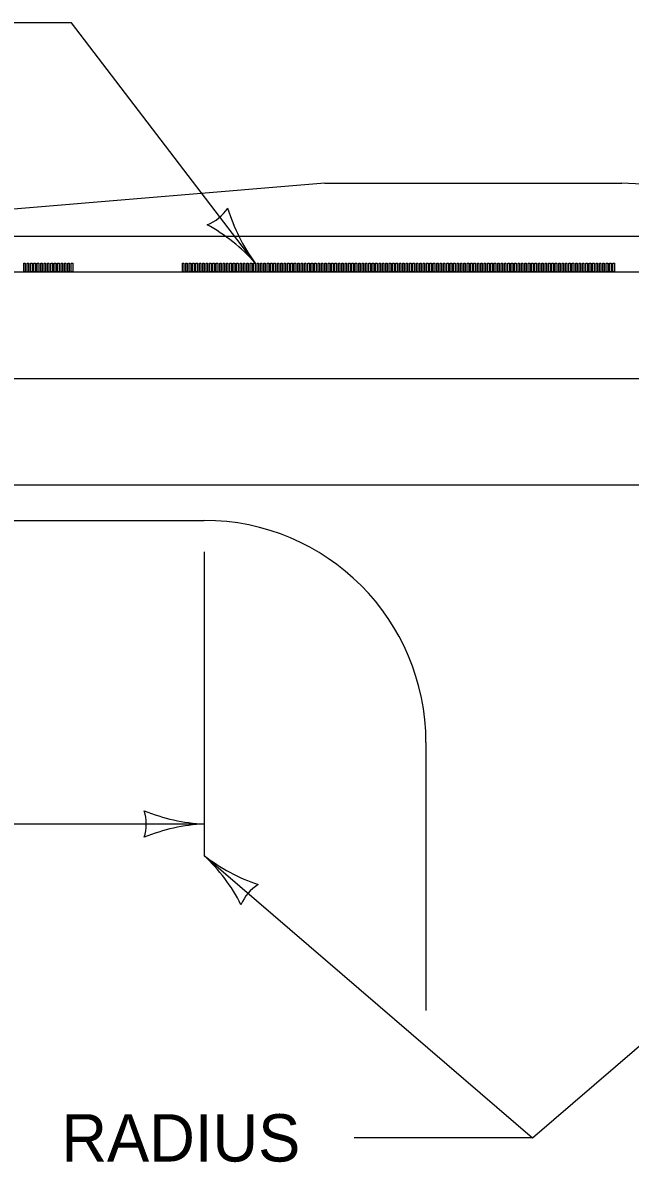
# Model space of a CAD drawing. Extents: x 49991.4 to 50021, y 49987.6 to 50011.4.
# Drawn here: x 50006.534 to 50007.305, y 49991.816 to 49993.26 of the extents above; entities that cross this region are included whole.
import ezdxf

# ---------------------------------------------------------------- set-up
doc = ezdxf.new("R2010")
doc.units = 0
for name, color, linetype in [('Level 1', 7, 'Continuous'), ('Level 2', 7, 'Continuous'), ('Level 3', 7, 'Continuous')]:
    doc.layers.add(name, color=color, linetype=linetype)

msp = doc.modelspace()

# ---------------------------------------------------------------- linework, layer by layer
at = {"layer": 'Level 1'}
for p, q in [((50006.9175, 49993.0571), (50005.5675, 49992.9446)), ((50006.9175, 49993.0571), (50007.294, 49993.0571)), ((50009.544, 49992.9446), (50007.294, 49993.0571)), ((50005.1251, 49992.9896), (50011.5103, 49992.9896)), ((50005.1251, 49992.9446), (50011.5103, 49992.9446)), ((50005.1251, 49992.8096), (50011.5103, 49992.8096)), ((50005.1253, 49992.6746), (50011.5103, 49992.6746)), ((50005.1253, 49992.6296), (50006.7645, 49992.6296)), ((50007.0457, 49992.3483), (50007.0457, 49992.0088))]:
    msp.add_line(p, q, dxfattribs=at)
for points in [[(50006.5374, 49992.9446), (50006.5355, 49992.9446), (50006.5355, 49992.9558), (50006.5374, 49992.9558)], [(50006.5417, 49992.9446), (50006.5398, 49992.9446), (50006.5398, 49992.9558), (50006.5417, 49992.9558)], [(50006.546, 49992.9446), (50006.5441, 49992.9446), (50006.5441, 49992.9558), (50006.546, 49992.9558)], [(50006.5503, 49992.9446), (50006.5484, 49992.9446), (50006.5484, 49992.9558), (50006.5503, 49992.9558)], [(50006.5546, 49992.9446), (50006.5527, 49992.9446), (50006.5527, 49992.9558), (50006.5546, 49992.9558)], [(50006.5589, 49992.9446), (50006.557, 49992.9446), (50006.557, 49992.9558), (50006.5589, 49992.9558)], [(50006.5632, 49992.9446), (50006.5613, 49992.9446), (50006.5613, 49992.9558), (50006.5632, 49992.9558)], [(50006.5675, 49992.9446), (50006.5656, 49992.9446), (50006.5656, 49992.9558), (50006.5675, 49992.9558)], [(50006.5718, 49992.9446), (50006.5699, 49992.9446), (50006.5699, 49992.9558), (50006.5718, 49992.9558)], [(50006.5761, 49992.9446), (50006.5742, 49992.9446), (50006.5742, 49992.9558), (50006.5761, 49992.9558)], [(50006.5804, 49992.9446), (50006.5785, 49992.9446), (50006.5785, 49992.9558), (50006.5804, 49992.9558)], [(50006.5847, 49992.9446), (50006.5828, 49992.9446), (50006.5828, 49992.9558), (50006.5847, 49992.9558)], [(50006.589, 49992.9446), (50006.5871, 49992.9446), (50006.5871, 49992.9558), (50006.589, 49992.9558)], [(50006.5933, 49992.9446), (50006.5914, 49992.9446), (50006.5914, 49992.9558), (50006.5933, 49992.9558)], [(50006.5976, 49992.9446), (50006.5957, 49992.9446), (50006.5957, 49992.9558), (50006.5976, 49992.9558)], [(50006.7387, 49992.9446), (50006.7368, 49992.9446), (50006.7368, 49992.9558), (50006.7387, 49992.9558)], [(50006.743, 49992.9446), (50006.7411, 49992.9446), (50006.7411, 49992.9558), (50006.743, 49992.9558)], [(50006.7473, 49992.9446), (50006.7454, 49992.9446), (50006.7454, 49992.9558), (50006.7473, 49992.9558)], [(50006.7516, 49992.9446), (50006.7497, 49992.9446), (50006.7497, 49992.9558), (50006.7516, 49992.9558)], [(50006.7559, 49992.9446), (50006.754, 49992.9446), (50006.754, 49992.9558), (50006.7559, 49992.9558)], [(50006.7602, 49992.9446), (50006.7583, 49992.9446), (50006.7583, 49992.9558), (50006.7602, 49992.9558)], [(50006.7645, 49992.9446), (50006.7626, 49992.9446), (50006.7626, 49992.9558), (50006.7645, 49992.9558)], [(50006.7688, 49992.9446), (50006.7669, 49992.9446), (50006.7669, 49992.9558), (50006.7688, 49992.9558)], [(50006.7731, 49992.9446), (50006.7712, 49992.9446), (50006.7712, 49992.9558), (50006.7731, 49992.9558)], [(50006.7774, 49992.9446), (50006.7755, 49992.9446), (50006.7755, 49992.9558), (50006.7774, 49992.9558)], [(50006.7817, 49992.9446), (50006.7798, 49992.9446), (50006.7798, 49992.9558), (50006.7817, 49992.9558)], [(50006.786, 49992.9446), (50006.7841, 49992.9446), (50006.7841, 49992.9558), (50006.786, 49992.9558)], [(50006.7903, 49992.9446), (50006.7884, 49992.9446), (50006.7884, 49992.9558), (50006.7903, 49992.9558)], [(50006.7946, 49992.9446), (50006.7927, 49992.9446), (50006.7927, 49992.9558), (50006.7946, 49992.9558)], [(50006.7989, 49992.9446), (50006.797, 49992.9446), (50006.797, 49992.9558), (50006.7989, 49992.9558)], [(50006.8032, 49992.9446), (50006.8013, 49992.9446), (50006.8013, 49992.9558), (50006.8032, 49992.9558)], [(50006.8075, 49992.9446), (50006.8056, 49992.9446), (50006.8056, 49992.9558), (50006.8075, 49992.9558)], [(50006.8118, 49992.9446), (50006.8099, 49992.9446), (50006.8099, 49992.9558), (50006.8118, 49992.9558)], [(50006.8161, 49992.9446), (50006.8142, 49992.9446), (50006.8142, 49992.9558), (50006.8161, 49992.9558)], [(50006.8204, 49992.9446), (50006.8185, 49992.9446), (50006.8185, 49992.9558), (50006.8204, 49992.9558)], [(50006.8247, 49992.9446), (50006.8228, 49992.9446), (50006.8228, 49992.9558), (50006.8247, 49992.9558)], [(50006.829, 49992.9446), (50006.8271, 49992.9446), (50006.8271, 49992.9558), (50006.829, 49992.9558)], [(50006.8333, 49992.9446), (50006.8314, 49992.9446), (50006.8314, 49992.9558), (50006.8333, 49992.9558)], [(50006.8376, 49992.9446), (50006.8357, 49992.9446), (50006.8357, 49992.9558), (50006.8376, 49992.9558)], [(50006.8419, 49992.9446), (50006.84, 49992.9446), (50006.84, 49992.9558), (50006.8419, 49992.9558)], [(50006.8462, 49992.9446), (50006.8443, 49992.9446), (50006.8443, 49992.9558), (50006.8462, 49992.9558)], [(50006.8505, 49992.9446), (50006.8486, 49992.9446), (50006.8486, 49992.9558), (50006.8505, 49992.9558)], [(50006.8548, 49992.9446), (50006.8529, 49992.9446), (50006.8529, 49992.9558), (50006.8548, 49992.9558)], [(50006.8591, 49992.9446), (50006.8572, 49992.9446), (50006.8572, 49992.9558), (50006.8591, 49992.9558)], [(50006.8634, 49992.9446), (50006.8615, 49992.9446), (50006.8615, 49992.9558), (50006.8634, 49992.9558)], [(50006.8677, 49992.9446), (50006.8658, 49992.9446), (50006.8658, 49992.9558), (50006.8677, 49992.9558)], [(50006.872, 49992.9446), (50006.8701, 49992.9446), (50006.8701, 49992.9558), (50006.872, 49992.9558)], [(50006.8763, 49992.9446), (50006.8744, 49992.9446), (50006.8744, 49992.9558), (50006.8763, 49992.9558)], [(50006.8806, 49992.9446), (50006.8787, 49992.9446), (50006.8787, 49992.9558), (50006.8806, 49992.9558)], [(50006.8849, 49992.9446), (50006.883, 49992.9446), (50006.883, 49992.9558), (50006.8849, 49992.9558)], [(50006.8892, 49992.9446), (50006.8873, 49992.9446), (50006.8873, 49992.9558), (50006.8892, 49992.9558)], [(50006.8935, 49992.9446), (50006.8916, 49992.9446), (50006.8916, 49992.9558), (50006.8935, 49992.9558)], [(50006.8978, 49992.9446), (50006.8959, 49992.9446), (50006.8959, 49992.9558), (50006.8978, 49992.9558)], [(50006.9021, 49992.9446), (50006.9002, 49992.9446), (50006.9002, 49992.9558), (50006.9021, 49992.9558)], [(50006.9064, 49992.9446), (50006.9045, 49992.9446), (50006.9045, 49992.9558), (50006.9064, 49992.9558)], [(50006.9107, 49992.9446), (50006.9088, 49992.9446), (50006.9088, 49992.9558), (50006.9107, 49992.9558)], [(50006.915, 49992.9446), (50006.9131, 49992.9446), (50006.9131, 49992.9558), (50006.915, 49992.9558)], [(50006.9193, 49992.9446), (50006.9174, 49992.9446), (50006.9174, 49992.9558), (50006.9193, 49992.9558)], [(50006.9236, 49992.9446), (50006.9217, 49992.9446), (50006.9217, 49992.9558), (50006.9236, 49992.9558)], [(50006.9279, 49992.9446), (50006.926, 49992.9446), (50006.926, 49992.9558), (50006.9279, 49992.9558)], [(50006.9322, 49992.9446), (50006.9303, 49992.9446), (50006.9303, 49992.9558), (50006.9322, 49992.9558)], [(50006.9365, 49992.9446), (50006.9346, 49992.9446), (50006.9346, 49992.9558), (50006.9365, 49992.9558)], [(50006.9408, 49992.9446), (50006.9389, 49992.9446), (50006.9389, 49992.9558), (50006.9408, 49992.9558)], [(50006.9451, 49992.9446), (50006.9432, 49992.9446), (50006.9432, 49992.9558), (50006.9451, 49992.9558)], [(50006.9494, 49992.9446), (50006.9475, 49992.9446), (50006.9475, 49992.9558), (50006.9494, 49992.9558)], [(50006.9537, 49992.9446), (50006.9518, 49992.9446), (50006.9518, 49992.9558), (50006.9537, 49992.9558)], [(50006.958, 49992.9446), (50006.9561, 49992.9446), (50006.9561, 49992.9558), (50006.958, 49992.9558)], [(50006.9623, 49992.9446), (50006.9604, 49992.9446), (50006.9604, 49992.9558), (50006.9623, 49992.9558)], [(50006.9666, 49992.9446), (50006.9647, 49992.9446), (50006.9647, 49992.9558), (50006.9666, 49992.9558)], [(50006.9709, 49992.9446), (50006.969, 49992.9446), (50006.969, 49992.9558), (50006.9709, 49992.9558)], [(50006.9752, 49992.9446), (50006.9733, 49992.9446), (50006.9733, 49992.9558), (50006.9752, 49992.9558)], [(50006.9795, 49992.9446), (50006.9776, 49992.9446), (50006.9776, 49992.9558), (50006.9795, 49992.9558)], [(50006.9838, 49992.9446), (50006.9819, 49992.9446), (50006.9819, 49992.9558), (50006.9838, 49992.9558)], [(50006.9881, 49992.9446), (50006.9862, 49992.9446), (50006.9862, 49992.9558), (50006.9881, 49992.9558)], [(50006.9924, 49992.9446), (50006.9905, 49992.9446), (50006.9905, 49992.9558), (50006.9924, 49992.9558)], [(50006.9967, 49992.9446), (50006.9948, 49992.9446), (50006.9948, 49992.9558), (50006.9967, 49992.9558)], [(50007.001, 49992.9446), (50006.9991, 49992.9446), (50006.9991, 49992.9558), (50007.001, 49992.9558)], [(50007.0053, 49992.9446), (50007.0034, 49992.9446), (50007.0034, 49992.9558), (50007.0053, 49992.9558)], [(50007.0096, 49992.9446), (50007.0077, 49992.9446), (50007.0077, 49992.9558), (50007.0096, 49992.9558)], [(50007.0139, 49992.9446), (50007.012, 49992.9446), (50007.012, 49992.9558), (50007.0139, 49992.9558)], [(50007.0182, 49992.9446), (50007.0163, 49992.9446), (50007.0163, 49992.9558), (50007.0182, 49992.9558)], [(50007.0225, 49992.9446), (50007.0206, 49992.9446), (50007.0206, 49992.9558), (50007.0225, 49992.9558)], [(50007.0268, 49992.9446), (50007.0249, 49992.9446), (50007.0249, 49992.9558), (50007.0268, 49992.9558)], [(50007.0311, 49992.9446), (50007.0292, 49992.9446), (50007.0292, 49992.9558), (50007.0311, 49992.9558)], [(50007.0354, 49992.9446), (50007.0335, 49992.9446), (50007.0335, 49992.9558), (50007.0354, 49992.9558)], [(50007.0397, 49992.9446), (50007.0378, 49992.9446), (50007.0378, 49992.9558), (50007.0397, 49992.9558)], [(50007.044, 49992.9446), (50007.0421, 49992.9446), (50007.0421, 49992.9558), (50007.044, 49992.9558)], [(50007.0483, 49992.9446), (50007.0464, 49992.9446), (50007.0464, 49992.9558), (50007.0483, 49992.9558)], [(50007.0526, 49992.9446), (50007.0507, 49992.9446), (50007.0507, 49992.9558), (50007.0526, 49992.9558)], [(50007.0569, 49992.9446), (50007.055, 49992.9446), (50007.055, 49992.9558), (50007.0569, 49992.9558)], [(50007.0612, 49992.9446), (50007.0593, 49992.9446), (50007.0593, 49992.9558), (50007.0612, 49992.9558)], [(50007.0655, 49992.9446), (50007.0636, 49992.9446), (50007.0636, 49992.9558), (50007.0655, 49992.9558)], [(50007.0698, 49992.9446), (50007.0679, 49992.9446), (50007.0679, 49992.9558), (50007.0698, 49992.9558)], [(50007.0741, 49992.9446), (50007.0722, 49992.9446), (50007.0722, 49992.9558), (50007.0741, 49992.9558)], [(50007.0784, 49992.9446), (50007.0765, 49992.9446), (50007.0765, 49992.9558), (50007.0784, 49992.9558)], [(50007.0827, 49992.9446), (50007.0808, 49992.9446), (50007.0808, 49992.9558), (50007.0827, 49992.9558)], [(50007.087, 49992.9446), (50007.0851, 49992.9446), (50007.0851, 49992.9558), (50007.087, 49992.9558)], [(50007.0913, 49992.9446), (50007.0894, 49992.9446), (50007.0894, 49992.9558), (50007.0913, 49992.9558)], [(50007.0956, 49992.9446), (50007.0937, 49992.9446), (50007.0937, 49992.9558), (50007.0956, 49992.9558)], [(50007.0999, 49992.9446), (50007.098, 49992.9446), (50007.098, 49992.9558), (50007.0999, 49992.9558)], [(50007.1042, 49992.9446), (50007.1023, 49992.9446), (50007.1023, 49992.9558), (50007.1042, 49992.9558)], [(50007.1085, 49992.9446), (50007.1066, 49992.9446), (50007.1066, 49992.9558), (50007.1085, 49992.9558)], [(50007.1128, 49992.9446), (50007.1109, 49992.9446), (50007.1109, 49992.9558), (50007.1128, 49992.9558)], [(50007.1171, 49992.9446), (50007.1152, 49992.9446), (50007.1152, 49992.9558), (50007.1171, 49992.9558)], [(50007.1214, 49992.9446), (50007.1195, 49992.9446), (50007.1195, 49992.9558), (50007.1214, 49992.9558)], [(50007.1257, 49992.9446), (50007.1238, 49992.9446), (50007.1238, 49992.9558), (50007.1257, 49992.9558)], [(50007.13, 49992.9446), (50007.1281, 49992.9446), (50007.1281, 49992.9558), (50007.13, 49992.9558)], [(50007.1343, 49992.9446), (50007.1324, 49992.9446), (50007.1324, 49992.9558), (50007.1343, 49992.9558)], [(50007.1386, 49992.9446), (50007.1367, 49992.9446), (50007.1367, 49992.9558), (50007.1386, 49992.9558)], [(50007.1429, 49992.9446), (50007.141, 49992.9446), (50007.141, 49992.9558), (50007.1429, 49992.9558)], [(50007.1472, 49992.9446), (50007.1453, 49992.9446), (50007.1453, 49992.9558), (50007.1472, 49992.9558)], [(50007.1515, 49992.9446), (50007.1496, 49992.9446), (50007.1496, 49992.9558), (50007.1515, 49992.9558)], [(50007.1558, 49992.9446), (50007.1539, 49992.9446), (50007.1539, 49992.9558), (50007.1558, 49992.9558)], [(50007.1601, 49992.9446), (50007.1582, 49992.9446), (50007.1582, 49992.9558), (50007.1601, 49992.9558)], [(50007.1644, 49992.9446), (50007.1625, 49992.9446), (50007.1625, 49992.9558), (50007.1644, 49992.9558)], [(50007.1687, 49992.9446), (50007.1668, 49992.9446), (50007.1668, 49992.9558), (50007.1687, 49992.9558)], [(50007.173, 49992.9446), (50007.1711, 49992.9446), (50007.1711, 49992.9558), (50007.173, 49992.9558)], [(50007.1773, 49992.9446), (50007.1754, 49992.9446), (50007.1754, 49992.9558), (50007.1773, 49992.9558)], [(50007.1816, 49992.9446), (50007.1797, 49992.9446), (50007.1797, 49992.9558), (50007.1816, 49992.9558)], [(50007.1859, 49992.9446), (50007.184, 49992.9446), (50007.184, 49992.9558), (50007.1859, 49992.9558)], [(50007.1902, 49992.9446), (50007.1883, 49992.9446), (50007.1883, 49992.9558), (50007.1902, 49992.9558)], [(50007.1945, 49992.9446), (50007.1926, 49992.9446), (50007.1926, 49992.9558), (50007.1945, 49992.9558)], [(50007.1988, 49992.9446), (50007.1969, 49992.9446), (50007.1969, 49992.9558), (50007.1988, 49992.9558)], [(50007.2031, 49992.9446), (50007.2012, 49992.9446), (50007.2012, 49992.9558), (50007.2031, 49992.9558)], [(50007.2074, 49992.9446), (50007.2055, 49992.9446), (50007.2055, 49992.9558), (50007.2074, 49992.9558)], [(50007.2117, 49992.9446), (50007.2098, 49992.9446), (50007.2098, 49992.9558), (50007.2117, 49992.9558)], [(50007.216, 49992.9446), (50007.2141, 49992.9446), (50007.2141, 49992.9558), (50007.216, 49992.9558)], [(50007.2203, 49992.9446), (50007.2184, 49992.9446), (50007.2184, 49992.9558), (50007.2203, 49992.9558)], [(50007.2246, 49992.9446), (50007.2227, 49992.9446), (50007.2227, 49992.9558), (50007.2246, 49992.9558)], [(50007.2289, 49992.9446), (50007.227, 49992.9446), (50007.227, 49992.9558), (50007.2289, 49992.9558)], [(50007.2332, 49992.9446), (50007.2313, 49992.9446), (50007.2313, 49992.9558), (50007.2332, 49992.9558)], [(50007.2375, 49992.9446), (50007.2356, 49992.9446), (50007.2356, 49992.9558), (50007.2375, 49992.9558)], [(50007.2418, 49992.9446), (50007.2399, 49992.9446), (50007.2399, 49992.9558), (50007.2418, 49992.9558)], [(50007.2461, 49992.9446), (50007.2442, 49992.9446), (50007.2442, 49992.9558), (50007.2461, 49992.9558)], [(50007.2504, 49992.9446), (50007.2485, 49992.9446), (50007.2485, 49992.9558), (50007.2504, 49992.9558)], [(50007.2547, 49992.9446), (50007.2528, 49992.9446), (50007.2528, 49992.9558), (50007.2547, 49992.9558)], [(50007.259, 49992.9446), (50007.2571, 49992.9446), (50007.2571, 49992.9558), (50007.259, 49992.9558)], [(50007.2633, 49992.9446), (50007.2614, 49992.9446), (50007.2614, 49992.9558), (50007.2633, 49992.9558)], [(50007.2676, 49992.9446), (50007.2657, 49992.9446), (50007.2657, 49992.9558), (50007.2676, 49992.9558)], [(50007.2719, 49992.9446), (50007.27, 49992.9446), (50007.27, 49992.9558), (50007.2719, 49992.9558)], [(50007.2762, 49992.9446), (50007.2743, 49992.9446), (50007.2743, 49992.9558), (50007.2762, 49992.9558)], [(50007.2805, 49992.9446), (50007.2786, 49992.9446), (50007.2786, 49992.9558), (50007.2805, 49992.9558)], [(50007.2848, 49992.9446), (50007.2829, 49992.9446), (50007.2829, 49992.9558), (50007.2848, 49992.9558)]]:
    msp.add_lwpolyline(points, close=True, dxfattribs=at)
msp.add_arc((50006.7644, 49992.3483), 0.2813, 359.9898, 89.9898, dxfattribs=at)
at = {"layer": 'Level 3'}
for p, q in [((50006.5961, 49993.2602), (50005.6479, 49993.2602)), ((50006.829, 49992.9558), (50006.5961, 49993.2602)), ((50006.7644, 49992.5896), (50006.7644, 49992.205)), ((50006.7644, 49992.2449), (50006.0761, 49992.2449)), ((50006.7644, 49992.205), (50007.1807, 49991.8472)), ((50007.1807, 49991.8472), (50007.597, 49992.205)), ((50007.1807, 49991.8472), (50006.9548, 49991.8472))]:
    msp.add_line(p, q, dxfattribs=at)
for centre, radius, start, end in [((50006.7483, 49993.0554), 0.0548, 291.1688, 326.8911), ((50007.017, 49993.0934), 0.233, 196.9528, 216.2026), ((50006.6622, 49992.8088), 0.2223, 41.3904, 61.5739), ((50006.7735, 49992.4671), 0.2223, 247.456, 267.6395), ((50006.6361, 49992.2449), 0.0548, 342.1388, 17.8612), ((50006.7759, 49992.0122), 0.233, 92.8273, 112.0772), ((50006.6126, 49992.0425), 0.2223, 26.7784, 46.9619), ((50006.9073, 49992.389), 0.233, 232.1497, 251.3996), ((50006.8616, 49992.1214), 0.0548, 121.4612, 157.1836)]:
    msp.add_arc(centre, radius, start, end, dxfattribs=at)

# ---------------------------------------------------------------- texts
at = {"layer": 'Level 2'}
msp.add_text('RADIUS', height=0.06, rotation=359.9999, dxfattribs=at).set_placement((50006.5832, 49991.8172))

doc.saveas('drawing.dxf')
